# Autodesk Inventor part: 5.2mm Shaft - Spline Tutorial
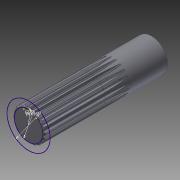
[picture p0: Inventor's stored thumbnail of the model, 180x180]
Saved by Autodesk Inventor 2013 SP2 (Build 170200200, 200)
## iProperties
Created: 2020-02
Part Number: 5.2mm Shaft - Spline Tutorial
Material: Steel
Document SubType Name: Modeling
Designer: DELL
Density: 1 g/cm^3
CustomPartVersion: 1
Author: DELL
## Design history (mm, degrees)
sketch "Sketch3"
  geometry: C1 r 2.6 at (0, 0); 1 further point
  constraints: 1 centre point, 1 coincident
  dimensions: "d16" = 5.2 diameter of C1
extrude "Extrusion1" new body sketch "Sketch3" distance "d18" = 20; taper "d19" = 0 deg
chamfer "Chamfer4" distance "d21" = 0.25; stored, may be unused: second distance "d22" = 2, angle "d23" = 45 deg
sketch "Sketch4"
  geometry: L1 (0, 0)-(1.12, 2.704); L2 (0, -3.751)-(0, 3.779) reference; L3 (0, 0)-(-1.12, 2.704); L4 (0.643, 1.552)-(-1.571, 2.469); C1 r 2.375 at (0, 0); C2 r 2.475 at (0, 0); C3 r 2.183 at (0, 0); C4 r 1.68 at (0, 0); 1 further point
  constraints: 6 end point, 4 centre point, 4 coincident, 1 perpendicular, 1 point on line, 1 tangent
  dimensions: "d46" = 4.75 diameter of C1; "d48" = 4.95 diameter of C2; "d49" = 4.367 diameter of C3; "d50" = 3.359 diameter of C4; "d52" = 22.5 deg angle of L1 L2; "d53" = 45 deg angle of L1 L3
sketch "Sketch5"
  geometry: L1 (0, -1.686)-(-0.333, -2.668); L2 (0, -1.686)-(0.336, -2.675); L3 (0, -3.751)-(0, 3.779) reference; 5 further points
  constraints: 4 end point, 2 other
  dimensions: "d54" = 1.6862 distance of L1.start point (0, 0); "d55" = 18.75 deg angle of L2 L3; "d56" = 18.75 deg angle of L3 L1 (= d55); "d57" = 37.5 deg angle of L2 L1 (derived)
node "Involute Splining9"
sketch "Sketch6" dims "d64" = 4.61623 (derived)
  geometry: C1 r 3.5 at (0, 0); A1 r 2.308 centre (0, 0) between (0.414, 2.271) and (0.308, 2.287) reference; A2 r 1.037 centre (-0.708, 1.95) between (0.259, 2.327) and (0.255, 2.336) reference; A3 r 0.063 centre (0.317, 2.349) between (0.259, 2.327) and (0.308, 2.287) reference; A4 r 0.062 centre (0.425, 2.332) between (0.414, 2.271) and (0.473, 2.293) reference; A5 r 1.037 centre (1.276, 1.636) between (0.48, 2.301) and (0.473, 2.293) reference; A6 r 1.037 centre (1.276, 1.636) between (0.706, 2.502) and (0.473, 2.293) reference; A7 r 2.6 centre (0, 0) between (0.706, 2.502) and (0.102, 2.598); 2 further points
  constraints: 3 coincident, 2 centre point, 2 point on circle, 4 other
  dimensions: "d61" = 7 diameter of C1; "d63" = 2.6 radius of A7 (derived)
body "Solid2"
feature "Shaft Groove"
